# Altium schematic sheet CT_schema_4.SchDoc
size 284 x 135 mm
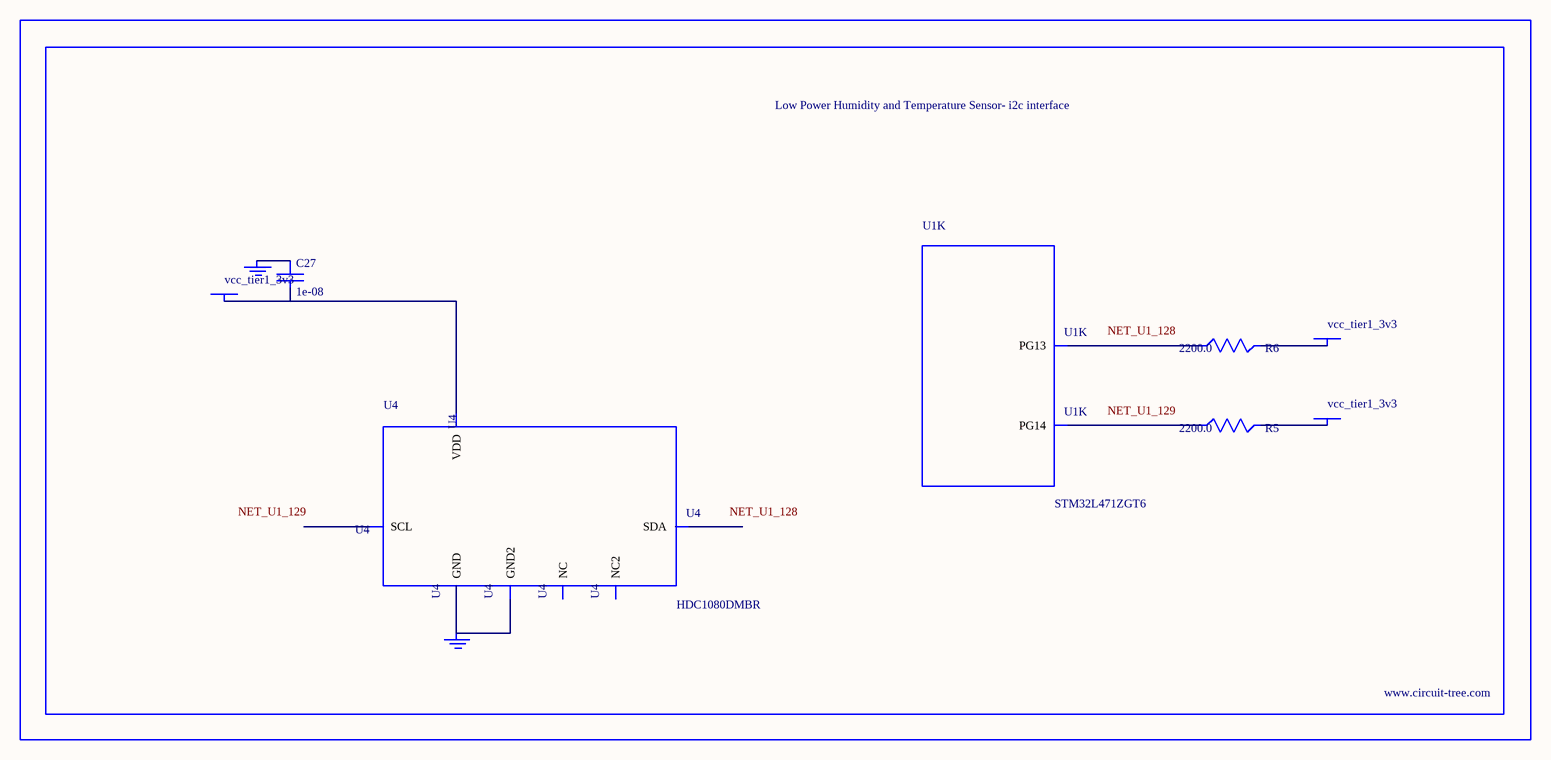
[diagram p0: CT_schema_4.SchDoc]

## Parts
BORDER3  (no value)
C27  1e-08  [C0402]
GND_INSTANCE_3_0  (no value)
GND_INSTANCE_3_1  (no value)
POWER_INSTANCE_3_0  vcc_tier1_3v3
POWER_INSTANCE_3_1  vcc_tier1_3v3
POWER_INSTANCE_3_2  vcc_tier1_3v3
R5  2200.0  [R0603]
R6  2200.0  [R0603]
U1  STM32L471ZGT6  [LQFP144]  (part K of 14)
U4  HDC1080DMBR  [WSON-6]

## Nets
NetC27_1: C27.1 GND_INSTANCE_3_0.0(GND)
NetC27_2: C27.2 POWER_INSTANCE_3_0.0(PWR) U4.5(VDD)
NetGND_INSTANCE_3_1_0: GND_INSTANCE_3_1.0(GND) U4.2(GND) U4.PAD(GND2)
NetPOWER_INSTANCE_3_1_0: POWER_INSTANCE_3_1.0(PWR) R6.2
NetPOWER_INSTANCE_3_2_0: POWER_INSTANCE_3_2.0(PWR) R5.2
NetR5_1: R5.1 U1.129(PG14)
NetR6_1: R6.1 U1.128(PG13)

Not connected (* = marked no-connect by the designer): U4 1(SDA) 3(NC) 4(NC2) 6(SCL)

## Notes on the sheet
- Labels drawn without touching a wire or pin: NET_U1_128, NET_U1_129

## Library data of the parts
BORDER3 = BORDER_PAGE3
C27 = C0402C103K3RAC
GND_INSTANCE_3_0 GND_INSTANCE_3_1 = GND
POWER_INSTANCE_3_0-POWER_INSTANCE_3_2 = PWR
R5 R6 = RC0603JR-072K2L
